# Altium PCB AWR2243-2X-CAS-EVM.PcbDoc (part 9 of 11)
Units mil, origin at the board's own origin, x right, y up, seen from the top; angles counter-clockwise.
Board outline 5118.11 x 3937.01 mil, 8 copper layers (Layer 1 - Top Layer, Layer 2 - GND, Layer 3 - Signal (Sensitive), Layer 4 - GND / Signal, Layer 5 - Signal, Layer 6 - PWR / Signal, Layer 7 - GND, Layer 8 - Bottom Layer), stack 54.8 mil thick; 629 components, 407 nets, 2243 pads, 3950 vias.
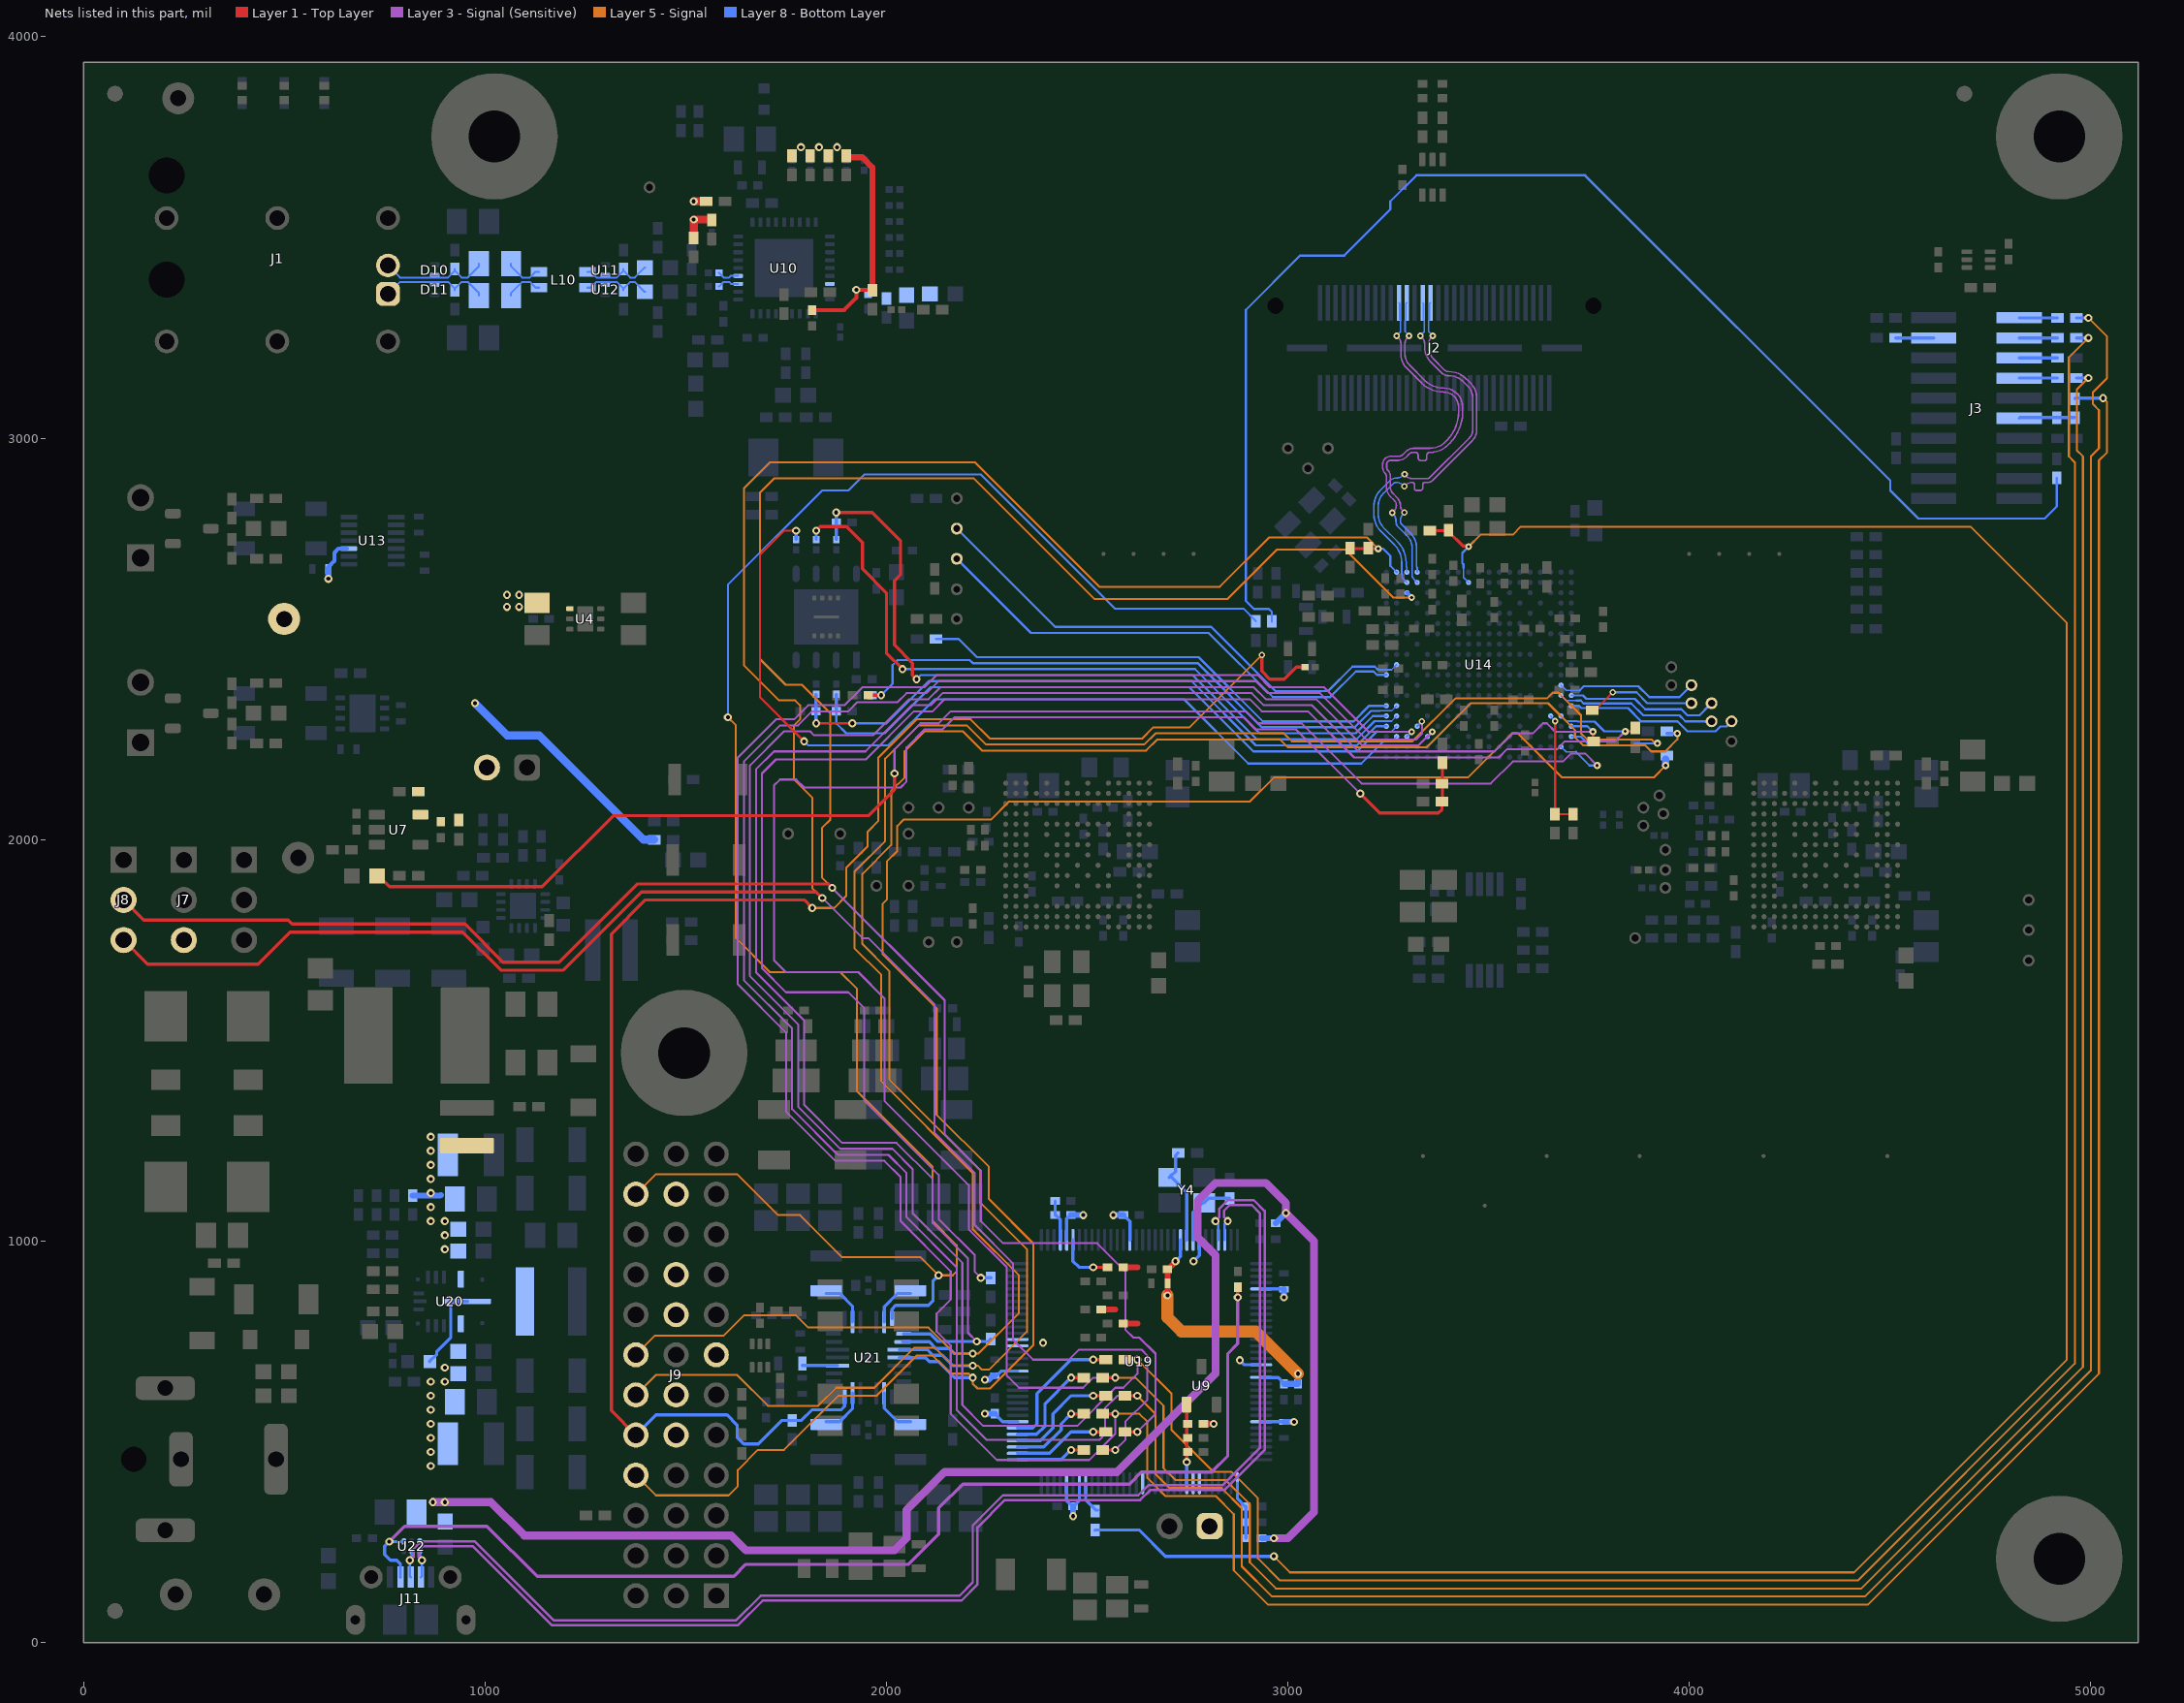
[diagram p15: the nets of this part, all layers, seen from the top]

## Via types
v1: diameter 13.78, hole 5.91, Layer 1 - Top Layer to Layer 2 - GND, tented top, 2104 vias
v2: diameter 20, hole 10, Layer 1 - Top Layer to Layer 8 - Bottom Layer, tented both sides, 831 vias
v3: diameter 7.87, hole 3.94, Layer 1 - Top Layer to Layer 2 - GND, tented top, 510 vias
v4: diameter 12, hole 6, Layer 1 - Top Layer to Layer 8 - Bottom Layer, tented both sides, 176 vias
v5: diameter 16, hole 8, Layer 1 - Top Layer to Layer 8 - Bottom Layer, tented both sides, 138 vias
v6: diameter 13.78, hole 5.91, Layer 1 - Top Layer to Layer 2 - GND, tented both sides, 88 vias
v7: diameter 18, hole 8, Layer 1 - Top Layer to Layer 8 - Bottom Layer, tented both sides, 41 vias
v8: diameter 22, hole 12, Layer 1 - Top Layer to Layer 8 - Bottom Layer, tented both sides, 36 vias
v9: diameter 19.68, hole 7.87, Layer 1 - Top Layer to Layer 8 - Bottom Layer, tented both sides, 26 vias

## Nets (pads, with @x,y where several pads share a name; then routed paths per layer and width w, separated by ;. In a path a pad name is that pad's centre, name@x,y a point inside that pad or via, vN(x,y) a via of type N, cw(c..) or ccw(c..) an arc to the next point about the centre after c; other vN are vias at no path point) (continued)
SOC_LVDS_TX2_N: J2.40 U14.V4 | length 951.9
  Layer 3 - Signal (Sensitive) w4: v5(3259.5,2814.5) 3264.34,2819.34 ccw(c3250.69,2833) 3270,2833 ccw(c3253.1,2833) 3265.06,2844.94 3255.61,2854.39 cw(c3281.21,2880) 3245,2880 3245,2905.76 ccw(c3234.76,2905.76) 3242,2913 cw(c3256.49,2927.49) 3236,2927.49 3236,2935 cw(c3256,2935) 3256,2955 3274.93,2955 ccw(c3274.93,2972.07) 3287,2960 3294.93,2967.93 cw(c3312,2950.86) 3312,2975 3354,2975 ccw(c3354,3028.11) 3391.56,2990.56 3396.03,2995.03 ccw(c3326.1,3064.97) 3425,3064.97 3425,3078 ccw(c3388,3078) 3388,3115 cw(c3388,3192.6) 3333.13,3137.73 3295.91,3174.95 cw(c3330.96,3210) 3281.39,3210 3281.39,3235 ccw(c3258.32,3235) v5@3274.64,3251.31 ; v5(3270.94,3255) v5@3274.63,3251.31
  Layer 8 - Bottom Layer w4: v5(3259.5,2814.5) 3261.93,2812.07 cw(c3244.86,2795) 3269,2795 3269,2792.78 ccw(c3289.12,2792.78) 3274.89,2778.55 3298.22,2755.22 cw(c3272.07,2729.07) 3309.05,2729.07 3309.05,2661 ccw(c3326.77,2661) 3314.25,2648.46 U14.V4@3321.85,2640.87 ; v5(3270.94,3255) 3270.94,3256 3280.67,3265.72 3280.67,3293.5 3278.56,3295.61 3278.56,3335.66 J2.40@3276.42,3337.8
SOC_LVDS_TX2_P: J2.38 U14.W4 | length 952
  Layer 3 - Signal (Sensitive) w4: v5(3290,2815) 3285.66,2819.34 cw(c3299.31,2833) 3280,2833 ccw(c3253.1,2833) 3272.12,2852.02 3262.68,2861.46 cw(c3281.21,2880) 3255,2880 3255,2905.76 ccw(c3234.76,2905.76) 3249.07,2920.07 cw(c3256.49,2927.49) 3246,2927.49 3246,2935 cw(c3256,2935) 3256,2945 3274.93,2945 ccw(c3274.93,2972.07) 3294.07,2952.93 3302,2960.86 cw(c3312,2950.86) 3312,2965 3316.84,2965 cw(c3316.84,2957.34) 3324.5,2957.34 3324.5,2951.24 ccw(c3331.24,2951.24) 3331.24,2944.5 3340.5,2944.5 ccw(c3340.5,2949.5) 3345.5,2949.5 3345.5,2957.34 cw(c3353.16,2957.34) 3353.16,2965 3354,2965 ccw(c3354,3028.11) 3398.63,2983.49 3403.1,2987.96 ccw(c3326.1,3064.97) 3435,3064.97 3435,3078 ccw(c3388,3078) 3388,3125 cw(c3388,3192.6) 3340.2,3144.8 3302.98,3182.02 cw(c3330.96,3210) 3291.39,3210 3291.39,3235 cw(c3315.08,3235) 3298.33,3251.76 v5(3301.57,3255)
  Layer 8 - Bottom Layer w4: 3282.67,2786.33 3306,2763 cw(c3272.07,2729.07) 3320.05,2729.07 3320.05,2680.23 3321.85,2678.43 U14.W4@3321.85,2666.46 ; 3282.66,2786.34 cw(c3289.12,2792.78) 3280,2792.78 3280,2795 cw(c3304.14,2795) 3287.07,2812.07 v5(3290,2815) ; J2.38@3296.1,3337.8 3293.96,3335.66 3293.96,3295.61 3291.67,3293.31 3291.67,3265.91 3301.57,3256 v5(3301.57,3255)
SOC_LVDS_TX3_N: J2.34 U14.V3 | length 952.6
  Layer 3 - Signal (Sensitive) w4: v5@3289.5,2910.5 3294.34,2905.66 ccw(c3308,2919.31) 3308,2900 3348,2900 ccw(c3348,2907.24) 3353.11,2902.11 3452.22,3001.22 ccw(c3433.44,3020) 3460,3020 3460,3102.15 ccw(c3421.72,3102.15) 3448.79,3129.21 3437.56,3140.44 ccw(c3400,3102.89) 3400,3156 cw(c3400,3180.49) 3382.69,3163.17 3356.24,3189.62 ; v5(3330,3255) v5@3333.69,3251.31 ; v5@3333.7,3251.31 cw(c3317.38,3235) 3340.44,3235 3340.44,3227.75 ccw(c3394.37,3227.75) 3356.24,3189.62
  Layer 8 - Bottom Layer w4: 3253.69,2894.24 3230.72,2871.28 ccw(c3271.09,2830.91) 3214,2830.91 3214,2810 ccw(c3271.94,2810) 3230.97,2769.03 3264.7,2735.3 cw(c3219.4,2690) 3283.46,2690 3283.46,2661 ccw(c3301.18,2661) 3288.66,2648.46 U14.V3@3296.26,2640.87 ; 3253.69,2894.25 cw(c3270,2877.93) 3270,2901 ccw(c3270,2925.14) 3287.07,2908.07 v5@3289.5,2910.5 ; v5(3330,3255) 3330,3256 3339.72,3265.72 3339.72,3293.5 3337.61,3295.61 3337.61,3335.66 J2.34@3335.47,3337.8
  other v5: 3290.5,2910.5
SOC_LVDS_TX3_P: J2.32 U14.W3 | length 952.5
  Layer 3 - Signal (Sensitive) w4: v5(3290,2880) 3294.34,2884.34 cw(c3308,2870.69) 3308,2890 3310,2890 cw(c3310,2885) 3315,2885 3315,2875 ccw(c3320,2875) 3320,2870 3329.55,2870 ccw(c3329.55,2876.45) 3336,2876.45 3336,2885 cw(c3341,2885) 3341,2890 3348,2890 ccw(c3348,2907.24) 3360.19,2895.05 3459.29,2994.15 ccw(c3433.44,3020) 3470,3020 3470,3102.15 ccw(c3421.72,3102.15) 3455.86,3136.28 3444.63,3147.52 ccw(c3400,3102.89) 3400,3166 cw(c3400,3180.49) 3389.77,3170.23 3363.29,3196.71 cw(c3394.37,3227.75) 3350.44,3227.75 3350.44,3235 cw(c3374.14,3235) 3357.39,3251.76 v5(3360.63,3255)
  Layer 8 - Bottom Layer w4: v5(3290,2880) 3287.07,2882.93 ccw(c3270,2865.86) 3270,2890 ccw(c3270,2877.93) 3261.46,2886.46 3238.5,2863.5 ccw(c3271.09,2830.91) 3225,2830.91 3225,2810 ccw(c3271.94,2810) 3238.75,2776.81 3272.48,2743.08 cw(c3219.4,2690) 3294.46,2690 3294.46,2680.23 3296.26,2678.43 U14.W3@3296.26,2666.46 ; J2.32@3355.16,3337.8 3353.02,3335.66 3353.02,3295.61 3350.72,3293.31 3350.72,3265.91 3360.63,3256 v5(3360.63,3255)
SOC_MSS_SPIA_IRQ: TP16.1 U14.G18 | length 396.5
  Layer 8 - Bottom Layer w4: U14.G18@3680.12,2359.37 3692.91,2346.57 3717.95,2346.57
  Layer 8 - Bottom Layer w5.5: 3717.95,2346.57 3729.43,2346.57 3736.24,2339.76 3855.24,2339.76 3885,2310 3975,2310 3990,2295 TP16.1@4050,2295
SOC_MSS_SPIA_MISO: R34.1 TP14.1 | length 271.7
  Layer 1 - Top Layer w5.5: R34.1@3757.83,2322.69 3764.69,2322.69 v5(3809,2367)
  Layer 8 - Bottom Layer w5.5: v5(3809,2367) 3868,2367 3895,2340 TP14.1@4000,2340
SOC_MSS_SPIA_MOSI: TP13.1 U14.H18 | length 356
  Layer 8 - Bottom Layer w4: U14.H18@3680.12,2384.96 3692.91,2372.17 3726.51,2372.17
  Layer 8 - Bottom Layer w5.5: 3726.51,2372.17 3726.7,2372.17 3736.79,2382.26 3872.74,2382.26 3900,2355 3975,2355 4000,2380 TP13.1@4000,2385
SOC_MSS_SPIA_nCS0: TP17.1 U14.F19 | length 436.1
  Layer 8 - Bottom Layer w5.5: U14.F19@3705.71,2333.78 3724.61,2333.78 3730.63,2327.76 3847.24,2327.76 3880,2295 3970,2295 3995,2270 4065,2270 4077,2282 4092,2282 TP17.1@4105,2295
SOC_MSS_SPIA_SCLK: TP15.1 U14.G19 | length 380.1
  Layer 8 - Bottom Layer w5.5: U14.G19@3705.71,2359.37 3734.63,2359.37 3743.24,2350.76 3864.24,2350.76 3890,2325 3980,2325 3995,2310 4025,2310 4050,2335 TP15.1@4050,2340
SOC_MSS_UARTA_RX: J8.2 R80.1 U14.U3 | length 6777.7
  Layer 1 - Top Layer w8: J8.2@100,1850 150,1800 510,1800 520,1790 950,1790 1045,1695 1185,1695 1380,1890 1855,1890 v2(1865,1880) ; R80.1@2593.62,525 v2(2625,525)
  Layer 3 - Signal (Sensitive) w5: v2(1865,1880) 2145,1600 2145,1266.21 2235,1176.21 2235,1050 2290,995 2525,995 2595,925 2595,780 2615,760 2630,760 2670,720 2670,570 v2(2625,525)
  Layer 5 - Signal w5: v2(1865,1880) 1840,1905 1840,2030 1860,2050 1860,2315 1789,2386 1749,2386 1685,2450 1685,2865 1720,2900 2217.57,2900 2517.57,2600 2749.14,2600 2850,2600 2973,2723 3142,2723 3261.59,2603.41 v5(3308.13,2603.41)
  Layer 8 - Bottom Layer w10: U14.U3@3296.26,2615.28 v5(3308.13,2603.41)
SOC_nERROR_OUT: J9.15 R32.2 R225.1 U21.16 | length 4211
  Layer 1 - Top Layer w8: J9.15@1375.98,517.01 1315,577.99 1315,1765 1400,1850 1795,1850 v2(1815,1830) ; v5(2935,2460) 2935,2420 2955,2400 2990.39,2400 3020.39,2430 R32.2@3042.01,2430
  Layer 5 - Signal w5: v2(1815,1830) 1870,1830 1900,1860 1900,1930 1953,1983 1953,2020 1980,2047 1980,2205 2075,2300 2210,2300 2258,2252 2637,2252 2665,2280 2755,2280 v5(2935,2460)
  Layer 8 - Bottom Layer w8: J9.15@1375.98,517.01 1425.98,567 1603,567 1628.17,541.83 1628.17,511.83 1645,495 1681.38,495 1740,553.62 R225.1@1765.21,553.62 1788.62,553.62 1815,580 1887,580 1895.94,588.95 U21.16@1895.94,612.56
SOC_nRESET_FROM_EMU: R125.2 R142.1 | length 3448.3
  Layer 8 - Bottom Layer w5.5: R142.1@2960,2543.62 2960,2567.49 2952.49,2575 2915,2575 2895,2595 2895,3320 3030,3455 3140,3455 3255,3570 3255,3590 3320,3655 3740,3655 4500,2895 4500,2870 4570,2800 4885,2800 4915,2830 R125.2@4915,2901.38
SOC_nRESET_FROM_PMIC: J9.33 R143.1 U21.32 | length 4762
  Layer 5 - Signal w5: J9.33@1375.98,1117.01 1425.98,1167 1628,1167 1730,1065 1785,1065 1890,960 2085,960 v2(2130,915) 2165,915 2175,925 2175,990 2115,1050 2115,1185 1927,1373 1927,1628 1885,1670 1710,1670 1625,1755 1625,2285 v2(1605,2305)
  Layer 8 - Bottom Layer w5: v2(1605,2305) 1605,2635 1840,2870 1905,2870 1945,2910 2235,2910 2570,2575 2890,2575 2920,2545 R143.1@2920,2543.62
  Layer 8 - Bottom Layer w8: U21.32@2014.05,807.44 2014.06,831.06 2023,840 2105,840 2115.82,850.82 2115.82,900.82 v2(2130,915)
SOC_QSPI_CS: R234.2 R235.2 U14.F2 | length 1495.3
  Layer 1 - Top Layer w8: R235.2@1954.69,2360 1982.1,2360 1984.4,2362.3 v2(1986.69,2360)
  Layer 8 - Bottom Layer w4: 3228.29,2320.98 3257.87,2320.98 U14.F2@3270.67,2333.78
  Layer 8 - Bottom Layer w5.5: v2(1986.69,2360) 2015,2388.31 2015,2435 2027.66,2447.66 2207.34,2447.66 2215,2440 2775,2440 2935,2280 3165.83,2280 3206.81,2320.98 3228.29,2320.98
  Layer 8 - Bottom Layer w8: R234.2@1964.68,2360 v2(1986.69,2360)
SOC_QSPI_D0: R134.2 U14.C2 | length 2266.8
  Layer 1 - Top Layer w5.5: v2(1775,2770) 1745,2770 1685,2710 1685,2355 v2(1795,2245)
  Layer 8 - Bottom Layer w4: 3236.7,2244.21 3257.87,2244.21 U14.C2@3270.67,2257.01
  Layer 8 - Bottom Layer w5.5: v2@1800,2245 1800,2240 1805,2235 2005,2235 2120,2350 2435.83,2350 2741.36,2350 2901.36,2190 3182.48,2190 3236.7,2244.21
  Layer 8 - Bottom Layer w8: R134.2@1775,2747.99 v2(1775,2770)
SOC_QSPI_D1: R148.1 R151.1 U14.D2 | length 1617.9
  Layer 8 - Bottom Layer w4: 3222.29,2269.8 3257.87,2269.8 U14.D2@3270.67,2282.6
  Layer 8 - Bottom Layer w5.5: R151.1@1875.16,2320.16 1875.16,2289.84 1900,2265 1995,2265 2110,2380 2436.18,2380 2753.79,2380 2913.79,2220 3172.31,2220 3222.11,2269.8 3222.29,2269.8
  Layer 8 - Bottom Layer w8: R148.1@1875,2362.01 1875.16,2361.85 R151.1@1875.16,2320.16
SOC_QSPI_D2: R149.1 R152.1 U14.D1 | length 1621.8
  Layer 1 - Top Layer w5.5: v2(1825,2290) v2(1915,2290)
  Layer 8 - Bottom Layer w5.5: v2(1915,2290) 2000,2290 2105,2395 2454.68,2395 2760,2395 2920,2235 3171.75,2235 3219.35,2282.6 U14.D1@3245.08,2282.6
  Layer 8 - Bottom Layer w8: v2(1825,2290) 1824.84,2290.16 1824.84,2319.84 R152.1@1824.68,2320 1824.84,2320.16 1824.84,2361.85 R149.1@1825,2362.01
SOC_QSPI_D3: R130.1 R132.2 U14.E2 | length 1920.8
  Layer 1 - Top Layer w8: v2(1875,2815) 1965,2815 2035,2745 2035,2660 2020,2645 2020,2485 2065,2440 2065,2410 v2(2075,2400)
  Layer 8 - Bottom Layer w4: 3228.29,2295.39 3257.87,2295.39 U14.E2@3270.67,2308.19
  Layer 8 - Bottom Layer w5.5: v2(2075,2400) 2085,2410 2462.82,2410 2762.57,2410 2922.57,2250 3170.4,2250 3215.79,2295.39 3228.29,2295.39
  Layer 8 - Bottom Layer w8: R132.2@1875,2747.99 1875.16,2748.15 1875,2748.31 R130.1@1875,2784.69 ; v2(1875,2815) R130.1@1875,2784.69 ; R130.1@1875.31,2785 R130.1@1875,2784.69
SOC_QSPI_SCLK: R133.2 U14.E1 | length 1803.4
  Layer 1 - Top Layer w8: v2(1825,2770) 1835,2780 1900,2780 1940,2740 1940,2675 2000,2615 2000,2465 v2(2040,2425)
  Layer 8 - Bottom Layer w5.5: v2(2040,2425) 2768.79,2425 2928.79,2265 3168.48,2265 3211.67,2308.19 U14.E1@3245.08,2308.19
  Layer 8 - Bottom Layer w8: R133.2@1825,2747.99 v2(1825,2770)
SOC_SOP0_SOC_TDO: R37.1 R46.2 R48.1 R75.1 R118.2 | length 9701.8
  Layer 1 - Top Layer w8: R75.1@2538.62,660 v2(2570,660) ; v2(3180,2115) 3228,2067 3375,2067 3383.62,2075.62 R48.1@3383.62,2095 3385,2096.38 R37.1@3385,2191.38
  Layer 3 - Signal (Sensitive) w5: v2(2570,660) 2515,660 2490,635 2330,635 2300,665 2300,935 2205,1030 2205,1140 1995,1350 1995,1605 1930,1670 1750,1670 1720,1700 1720,2135 1735,2150 1775,2150 1795,2130 2035,2130 2050,2145 2050,2230 2095,2275 2140,2275 2170,2305 2890,2305 2920,2275 3020,2275 v2(3180,2115)
  Layer 5 - Signal w5: v2(2570,660) 2620,660 2690,590 2690,435 2720,405 2845,405 2905,345 2905,200 2970,135 4428.28,135 4980,686.72 4980,2955 4965,2970 4965,3121.38 v2(4993.62,3150)
  Layer 8 - Bottom Layer w8: R118.2@4963.62,3150 v2(4993.62,3150)
SOC_SOP1: R49.1 R50.2 U14.E17 | length 293.4
  Layer 1 - Top Layer w5.5: R49.1@3665,2063.62 R49.1@3665.18,2063.62 ; v5(3665.18,2295.39) R49.1@3665.18,2063.62 ; R50.2@3710,2063.62 R49.1@3665.18,2063.62
  Layer 8 - Bottom Layer w4: U14.E17@3654.53,2308.19 v5(3665.18,2295.39)
SOC_SOP2: R146.2 U14.F1 | length 1222.4
  Layer 8 - Bottom Layer w5.5: R146.2@2123.62,2500 2180,2500 2225,2455 2777.72,2455 2937.72,2295 3163.95,2295 3202.73,2333.78 U14.F1@3245.08,2333.78
SOC_SOP3_SOC_MSS_UARTB_TX: R19.2 R21.1 R228.1 U14.V9 | length 6347.7
  Layer 1 - Top Layer w8: R21.1@3353.62,2770 3398.62,2770 R19.2@3400,2771.38 3400,2767.44 3435.53,2731.91 3448.09,2731.91 v7(3450,2730)
  Layer 5 - Signal w5: v2(2965,215) 3005,175 4410,175 4940,705 4940,2540 4700,2780 3580,2780 3560,2760 3480,2760 v7(3450,2730)
  Layer 8 - Bottom Layer w4: 3437.01,2676.94 3437.01,2653.66 U14.V9@3449.8,2640.87
  Layer 8 - Bottom Layer w5.5: 3437.01,2676.94 3437.01,2685.68 3434.34,2688.35 3434.34,2714.34 v7(3450,2730)
  Layer 8 - Bottom Layer w8: R228.1@2519.37,280 R228.1@2520,280.63 2629.37,280.63 2695,215 v2(2965,215)
SOC_SOP4_SOC_MSS_UARTA_TX: J8.3 R20.1 R22.2 R82.1 U14.W2 | length 6991.3
  Layer 1 - Top Layer w8: J8.3@100,1750 160,1690 435,1690 515,1770 945,1770 1040,1675 1195,1675 1390,1870 1825,1870 v2(1840,1855) ; R82.1@2538.62,480 v2(2570,480) ; R22.2@3155,2726.62 3156.62,2725 v7(3225,2725)
  Layer 3 - Signal (Sensitive) w5: v2(1840,1855) 1940,1755 1955,1755 2120,1590 2120,1270 2220,1170 2220,1040 2315,945 2315,755 2365,705 2455,705 2480,730 2635,730 2650,715 2650,605 2595,550 2595,505 v2(2570,480)
  Layer 5 - Signal w5: v2(1840,1855) 1815,1880 1815,2105 1770,2150 1770,2285 1785,2300 1785,2335 1773,2347 1733,2347 1645,2435 1645,2875 1710,2940 2220,2940 2530,2630 2820,2630 2830,2630 2953,2753 3197,2753 v7(3225,2725)
  Layer 8 - Bottom Layer w5.5: v7(3225,2725) 3237,2725 3255,2707 3255,2682.13 U14.W2@3270.67,2666.46
SOC_SPIB_CS0: R36.1 R219.2 U14.D19 U21.2 | length 4305.1
  Layer 1 - Top Layer w5.5: v7(3759.58,2268.96) 3759.58,2246.8 R36.1@3761.38,2245
  Layer 3 - Signal (Sensitive) w5: v2(2225,750) 2203,772 2203,957 2115,1045 2115,1155 2025,1245 1890,1245 1795,1340 1795,1550 1675,1670 1675,2175 1720,2220 1947.57,2220 2062.57,2335 2110,2335 2140,2365 2910,2365 2940,2335 3060,2335 3175,2220 3515,2220 3560,2265 3610,2265 3635,2290 3645,2290 3666.04,2268.96 v7(3759.58,2268.96)
  Layer 8 - Bottom Layer w5.5: U14.D19@3705.71,2282.6 3745.94,2282.6 v7(3759.58,2268.96)
  Layer 8 - Bottom Layer w8: U21.2@2042.6,769.06 2109.94,769.06 2129,750 v2(2225,750) 2253.62,750 R219.2@2260,756.38
SOC_SPIB_CS1: R35.1 R216.2 U14.E18 | length 4115.7
  Layer 1 - Top Layer w5.5: v7(3840,2270) 3861.38,2270 R35.1@3866.38,2275
  Layer 3 - Signal (Sensitive) w5: v2(2235,908.62) 2220,923.62 2220,965 2130,1055 2130,1165 1945,1350 1945,1580 1905,1620 1750,1620 1690,1680 1690,2165 1725,2200 1948.79,2200 2068.79,2320 2115,2320 2145,2350 2905,2350 2935,2320 3050,2320 3165,2205 3525,2205 3545,2225 3670,2225 3690,2245 3815,2245 v7(3840,2270)
  Layer 8 - Bottom Layer w4: U14.E18@3680.12,2308.19 3692.91,2295.39 3721.2,2295.39 3722.5,2294.1
  Layer 8 - Bottom Layer w5.5: 3722.5,2294.1 3763.9,2294.1 3788,2270 v7(3840,2270)
  Layer 8 - Bottom Layer w8: v2(2235,908.62) R216.2@2260,908.62
SOC_SPIB_MISO: J9.21 U14.C19 U21.3 | length 5196.3
  Layer 5 - Signal w5: J9.21@1375.98,717.01 1423.98,765 1595,765 1645,815 1775,815 1805,785 2105,785 2170,720 v2(2215,720) 2229,720 2330,821 2330,915 2215,1030 2215,1170 1987,1398 1987,1663 1920,1730 1920,1920 1997,1997 1997,2202 2080,2285 2200,2285 2248,2237 2642,2237 2670,2265 2990,2265 3010,2245 3310,2245 3417,2352 3645,2352 3659,2366 3674,2366 3730,2310 3730,2265 3745,2250 3905,2250 3915,2240 v7(3920,2240)
  Layer 8 - Bottom Layer w5.5: U14.C19@3705.71,2257.01 3729.48,2257.01 3751.49,2235 3860,2235 3865,2240 v7(3920,2240)
  Layer 8 - Bottom Layer w8: U21.3@2040.63,749.37 2106.63,749.37 2123,733 2157,733 2170,720 v2(2215,720)
SOC_SPIB_MOSI: J9.12 R154.1 U21.5 | length 5023.7
  Layer 5 - Signal w5: J9.12@1375.98,417.01 1425.99,367 1607,367 1630,390 1630,430 1680,480 1745,480 1880,615 1975,615 2075,715 2115,715 2160,670 2205,670 v2(2215,660) 2215,645 2227,633 2258,633 2366,741 2366,994 2255,1105 2255,1185 2125,1315 2125,1580 1990,1715 1990,1840 2001,1851 2001,1946 2027,1972 2027,2034.5 2042.5,2050 2260,2050 2305,2095 2905,2095 2965,2155 3448,2155 3558,2265 3573,2265 3683,2155 3911,2155 v7(3941,2185)
  Layer 8 - Bottom Layer w8: U21.5@2031.77,710 2097,710 2107,700 2130,700 2170,660 v2(2215,660) ; R154.1@3941,2200.38 3940,2201.38 R154.1@3943.62,2205
  Layer 8 - Bottom Layer w18: v7(3941,2185) R154.1@3941,2200.38
SOC_SPIB_SCLK: J9.18 R153.1 U21.4 | length 5151.9
  Layer 5 - Signal w5: J9.18@1375.98,617.01 1425.98,667 1628,667 1705,590 1830,590 1875,635 1970,635 2070,735 2120,735 2165,690 v2(2215,690) 2228,690 2238,680 2255,680 2350,775 2350,980 2235,1095 2235,1175 2007,1403 2007,1673 1940,1740 1940,1915 2012,1987 2012,2122 2045,2155 2045,2220 2095,2270 2190,2270 2238,2222 2647,2222 2675,2250 2980,2250 3000,2230 3345,2230 3455,2340 3648,2340 3715,2273 3715,2255 3735,2235 3890,2235 3905,2220 3940,2220 3970,2250 v7(3970,2265)
  Layer 8 - Bottom Layer w8: U21.4@2031.77,729.68 2102.32,729.68 2116,716 2139,716 2165,690 v2(2215,690) ; R153.1@3943.62,2265 v7(3970,2265)
SOC_TCK: R78.1 R120.2 U14.C3 | length 9921.3
  Layer 1 - Top Layer w8: R78.1@2538.62,570 v2(2570,570)
  Layer 3 - Signal (Sensitive) w5: v2(2570,570) 2570,520 2505,455 2275,455 2160,570 2160,740 2125,775 2125,820 2160,855 2160,925 2035,1050 2035,1160 1995,1200 1872.57,1200 1750,1322.57 1750,1520 1630,1640 1630,2205 1725,2300 1770,2300 1805,2335 1895,2335 1940,2380 2043.79,2380 2095,2380 2125,2410 2925,2410 2955,2380 3090,2380 3201.12,2268.88 v5(3308.13,2268.88)
  Layer 5 - Signal w5: v2(2570,570) 2630,570 2650,550 2650,410 2695,365 2820,365 2865,320 2865,180 2950,95 4444.85,95 5020,670.15 5020,2945 5040,2965 5040,3090 v2(5030,3100)
  Layer 8 - Bottom Layer w5.5: U14.C3@3296.26,2257.01 v5(3308.13,2268.88)
  Layer 8 - Bottom Layer w8: R120.2@4960,3098.62 4961.38,3100 v2(5030,3100)
SOC_TDI: R73.1 R113.2 U14.C5 | length 9883.7
  Layer 1 - Top Layer w8: R73.1@2593.62,705 v2(2625,705)
  Layer 3 - Signal (Sensitive) w5: v2(2625,705) 2625,670 2590,635 2570,635 2475,540 2241,540 2189,592 2189,946 2065,1070 2065,1180 2015,1230 1885,1230 1780,1335 1780,1540 1660,1660 1660,2185 1745,2270 1810,2270 1820,2260 1966.21,2260 2056.21,2350 2105,2350 2135,2380 2915,2380 2945,2350 3070,2350 3185,2235 3325.43,2235 v5(3359.31,2268.88)
  Layer 5 - Signal w5: v2(2625,705) 2710,620 2710,530 2815,425 2860,425 2925,360 2925,210 2980,155 4420,155 4960,695 4960,2940 4945,2955 4945,3201.38 v2(4993.62,3250)
  Layer 8 - Bottom Layer w5.5: U14.C5@3347.44,2257.01 v5(3359.31,2268.88)
  Layer 8 - Bottom Layer w8: R113.2@4963.62,3250 v2(4993.62,3250)
SOC_TMS: R77.1 R110.2 U14.D4 | length 10077.5
  Layer 1 - Top Layer w8: R77.1@2593.62,615 v2(2625,615)
  Layer 3 - Signal (Sensitive) w5: v2(2625,615) 2575,615 2545,585 2545,520 2530,505 2250,505 2175,580 2175,935 2050,1060 2050,1170 2005,1215 1878.79,1215 1765,1328.79 1765,1530 1645,1650 1645,2195 1735,2285 1780,2285 1815,2320 1905,2320 1927.5,2342.5 2027.5,2342.5 2050,2365 2100,2365 2130,2395 2920,2395 2950,2365 3080,2365 3195,2250 3320,2250 3333.72,2263.72 v5(3333.72,2294.47)
  Layer 5 - Signal w5: v2(2625,615) 2670,570 2670,420 2705,385 2835,385 2885,335 2885,190 2960,115 4436.57,115 5000,678.43 5000,2955 5020,2975 5020,3070 5005,3085 5005,3115 5040,3150 5040,3253.62 v2(4993.62,3300)
  Layer 8 - Bottom Layer w5.5: U14.D4@3321.85,2282.6 v5(3333.72,2294.47)
  Layer 8 - Bottom Layer w8: R110.2@4963.62,3300 v2(4993.62,3300)
SPARE_0: J9.14
SPARE_1: J9.17
SPARE_2: J9.23
SPARE_3: J9.26
SPARE_4: J9.32
SPARE_5: J9.19
SW: C217.1 L20.1 U20.16 | length 211.3
  Layer 8 - Bottom Layer w8: C217.1@862.56,700 862.56,700.98 880,718.43 880,726 915,761 915,847.11 917.89,850 U20.16@956.32,850
SW_B1: L21.1 U21.11 | length 117.3
  Layer 8 - Bottom Layer w8: U21.11@1994.37,621.42 1994.37,583.63 2027.88,550.12 L21.1@2060,550.12
SW_B2: L22.1 U21.15 | length 117.9
  Layer 8 - Bottom Layer w8: L22.1@1850,550.12 1883.12,550.12 1915.63,582.63 U21.15@1915.63,621.42
SW_B3: L19.1 U21.27 | length 117.9
  Layer 8 - Bottom Layer w8: L19.1@1850,869.88 1883.12,869.88 1915.63,837.37 U21.27@1915.63,798.58
SW_B4: L18.1 U21.31 | length 117.3
  Layer 8 - Bottom Layer w8: U21.31@1994.37,798.58 1994.37,836.37 2027.88,869.88 L18.1@2060,869.88
TCK: J3.11 R120.1 R121.2 | length 139.1
  Layer 8 - Bottom Layer w8: J3.11@4821.5,3050 4822.87,3051.38 R120.1@4960,3051.38
TDI: J3.3 R113.1 | length 94.9
  Layer 8 - Bottom Layer w8: J3.3@4821.5,3250 R113.1@4916.38,3250
TDIS: J3.4 R114.2 | length 94.9
  Layer 8 - Bottom Layer w8: R114.2@4513.62,3250 J3.4@4608.5,3250
TDO: J3.7 R118.1 | length 94.9
  Layer 8 - Bottom Layer w8: J3.7@4821.5,3150 R118.1@4916.38,3150
TMS: J3.1 R110.1 | length 94.9
  Layer 8 - Bottom Layer w8: J3.1@4821.5,3300 R110.1@4916.38,3300
TRD1_N: L10.1 R100.1 R103.2 U11.2 | length 177.5
  Layer 8 - Bottom Layer w5: L10.1@1255.04,3414.69 1263.9,3414.69 1278.08,3400.5 1328.06,3400.5 R100.1@1345,3417.44 ; R100.1@1345,3421.38 R100.1@1345,3417.44 ; R103.2@1398.5,3425 1397.52,3425 1373.02,3400.5 1361.94,3400.5 R100.1@1345,3417.44
TRD1_P: L10.2 R106.2 R108.2 U12.2 | length 177.5
  Layer 8 - Bottom Layer w5: L10.2@1255.04,3375.32 1263.9,3375.32 1278.08,3389.5 1328.06,3389.5 R106.2@1345,3372.56 ; R106.2@1345,3368.62 R106.2@1345,3372.56 ; R108.2@1398.5,3365 1397.52,3365 1373.02,3389.5 1361.94,3389.5 R106.2@1345,3372.56
TRD2_N: C102.2 L10.4 | length 93.9
  Layer 8 - Bottom Layer w5: C102.2@1065,3435 1065,3428.5 1093,3400.5 1111.92,3400.5 1126.1,3414.69 L10.4@1134.96,3414.69
TRD2_P: C103.2 L10.3 | length 93.9
  Layer 8 - Bottom Layer w5: C103.2@1065,3355 1065.02,3361.52 1093,3389.5 1111.92,3389.5 1126.1,3375.32 L10.3@1134.96,3375.32
TRD3_N: C102.1 D10.1 J1.2 R101.2 | length 275
  Layer 8 - Bottom Layer w5: J1.2@758.42,3430.44 788.37,3400.5 908.06,3400.5 R101.2@925,3417.44 ; R101.2@925,3421.38 R101.2@925,3417.44 ; C102.1@985,3435 985,3428.5 957,3400.5 941.94,3400.5 R101.2@925,3417.44
TRD3_P: C103.1 D11.1 J1.1 R107.2 | length 275
  Layer 8 - Bottom Layer w5: J1.1@758.42,3359.57 788.35,3389.5 908.04,3389.5 R107.2@924.98,3372.56 ; R107.2@925,3368.62 925,3372.56 941.94,3389.5 957,3389.5 984.98,3361.52 C103.1@985,3355
TRD_N: R105.1 U10.13 | length 54.2
  Layer 8 - Bottom Layer w5: R105.1@1582.99,3412 1594.49,3400.5 1608,3400.5 1611.81,3404.32 U10.13@1630.83,3404.32
TRD_P: R109.1 U10.12 | length 54.6
  Layer 8 - Bottom Layer w5: R109.1@1582.99,3378 1594.49,3389.5 1608,3389.5 1612.87,3384.63 U10.12@1630.83,3384.63
VBAT: C16.1 C121.1 C193.1 C203.1 C206.1 C209.1 C214.1 C220.1 C224.1 C227.1 J7.3 L4.2 R169.2 R208.1 TP9.1 U4.1 U13.10 U20.2 U20.14 | length 764.2
  Layer 8 - Bottom Layer w10: C121.1@610,2675 610,2679.5 625,2694.5 625,2715 635.28,2725.28 655.91,2725.28 U13.10@655.94,2725.32
  Layer 8 - Bottom Layer w15: v2(610,2650) C121.1@610,2675 ; R208.1@820,1113.62 888.62,1113.62 890,1115
  Layer 8 - Bottom Layer w20: v2(975,2340) 1055,2260 1135,2260 1395,2000 R169.2@1421.38,2000
  other v2: 865,440 865,475 865,510 865,545 865,580 865,615 865,650 900,650 900,685 900,980 900,1015 865,1050 900,1050 865,1085 865,1120 865,1155 865,1190 865,1225 865,1260 1055,2580 1085,2580 1055,2610 1085,2610
VBUS_1_DETECT: C238.2 R230.2 R231.1 U19.1 | length 146.8
  Layer 8 - Bottom Layer w8: U19.1@2874.09,396.85 U19.1@2874.09,396.85 2874.16,358.44 2893.35,339.25 C238.2@2895.31,339.25 R231.1@2895.31,260
VDDC: C76.2 C80.1 C221.2 C222.2 U19.87 U19.115 | length 715.2
  Layer 1 - Top Layer w8: C76.2@2699.69,930 C76.2@2700,930
  Layer 1 - Top Layer w15: C76.2@2699.69,930 C76.2@2700,929.69 ; v2(2700,865) C80.1@2700,895 2700,928.65 2720,948.65 v2(2720,950)
  Layer 5 - Signal w30: v2(2700,865) 2700,810 2735,775 2920,775 v2(3025,670)
  Layer 8 - Bottom Layer w8: v2(2720,950) 2732.36,962.36 U19.87@2732.36,1003.15 ; U19.115@2933.15,660.63 2976.02,660.63 2990,646.65 C222.2@2990,644.69
  Layer 8 - Bottom Layer w15: C222.2@2990,644.69 C221.2@3025,644.69 v2(3025,670)
VDDIO_ETH: C104.1 C106.2 C112.1 R3.2 R4.2 R5.2 R6.2 R7.2 R8.2 R9.2 R11.2 R17.1 R236.2 U10.34 | length 689.8
  Layer 1 - Top Layer w10: R17.1@1815,3319.37 1894.37,3319.37 1925,3350 v2(1925,3370) 1963.62,3370 R11.2@1965,3368.62
  Layer 1 - Top Layer w15: R6.2@1900,3703.62 1903.62,3700 1940,3700 1965,3675 R11.2@1965,3368.62
  Layer 1 - Top Layer w20: R9.2@1520,3498.62 v2(1520,3545) 1563.62,3545 R8.2@1565,3543.62 ; v2(1520,3590) R7.2@1551.38,3590
  other v2: 1787,3725 1832,3725 1877,3725
VOUT_LDO: C84.1 U21.20 | length 88.2
  Layer 8 - Bottom Layer w8: C84.1@1790,690.31 U21.20@1878.23,690.32
VPP_EN: R55.2 U14.B18 | length 3511.9
  Layer 1 - Top Layer w8: R55.2@737.48,1910 737.48,1907.52 762,1883 1143,1883 1320,2060 1955,2060 2020,2125 v2(2020,2165)
  Layer 3 - Signal (Sensitive) w5: v2(2020,2165) 2020,2225 2085,2290 2130,2290 2160,2320 2895,2320 2925,2290 3033.79,2290 3183.79,2140 3505,2140 3560,2195 3685,2195 3705,2215 3740,2215 v7(3770,2185)
  Layer 8 - Bottom Layer w4: U14.B18@3680.12,2231.42 3692.91,2218.62 3717.49,2218.62
  Layer 8 - Bottom Layer w5.5: 3717.49,2218.62 3751.11,2185 v7(3770,2185)
VPP_LDO_OUT: C47.1 C49.1 P1.2 R51.2 U7.5
VTREF: J3.5 R117.1 | length 94.9
  Layer 8 - Bottom Layer w8: J3.5@4821.5,3200 R117.1@4916.38,3200
XDS_3V3: C205.2 C210.1 C218.1 C225.2 C228.1 C237.2 P2.1 R62.2 R69.2 R71.2 R79.2 R211.2 U19.7 U19.8 U19.16 U19.26 U19.28 U19.39 U19.47 U19.51 U19.52 U19.69 U19.79 U19.90 U19.101 U19.113 U19.122 | length 933.7
  Layer 1 - Top Layer w15: R69.2@2534.69,830 2570,830 ; R71.2@2589.69,795 2625,795 ; R62.2@2589.69,935 2625,935 ; R79.2@2789.69,545 v2(2815,545)
  Layer 8 - Bottom Layer w8: C225.2@2270,570.31 2270,570 2289.54,550.46 2303.29,550.46 2303.35,550.39 U19.39@2326.85,550.39 ; C218.1@2270,665 2274.5,665 2285.88,676.38 U19.47@2326.85,676.38 ; U19.28@2448.9,396.85 2448.9,353.82 2462.72,340 C237.2@2464.68,340 2466.65,340 2480.39,353.74 U19.26@2480.39,396.85 ; U19.69@2448.9,1003.15 2448.9,1056.18 2457.72,1065 R211.2@2459.68,1065 ; C205.2@2590,1065 2606.38,1048.62 U19.79@2606.38,1003.15 ; v2(2765,950) 2779.61,964.61 U19.90@2779.6,1003.15 ; v2(2880,703.5) 2891.38,692.13 U19.113@2933.15,692.13 ; U19.122@2933.15,550.39 2933.21,550.33 2989.67,550.33 C228.1@2990,550 ; U19.101@2933.15,881.1 C210.1@2990,881.1
  Layer 8 - Bottom Layer w15: v2(2245,570.31) C225.2@2270,570.31 ; v2(2245,655) 2255,655 2265,665 C218.1@2270,665 ; R211.2@2459.68,1065 v2(2490,1065) ; v2(2464.69,315) C237.2@2464.68,340 ; v2(2565,1065) C205.2@2590,1065 ; C228.1@2990,550 v2(3015,550) ; v2(2990,860) C210.1@2990,880
  other v2: 2390,747
XDSET_1_D_N: J11.2 U19.93 U22.1 | length 3368.8
  Layer 3 - Signal (Sensitive) w6: v2(843,205) 834,214 834,229 845,240 970,240 1167,43 1629.97,43 1691.97,105 2186.97,105 2227,145.03 2227,287 2295,355 2631.97,355 2656.97,380 2841.97,380 2942,480.03 2942,1074.97 2914.97,1102 2850.03,1102 2829,1080.97 2829,1060 2819.45,1050.45 v2(2819.45,1050)
  Layer 8 - Bottom Layer w6: U22.1@839.68,229.17 837.69,227.17 837.69,210.31 v2(843,205) 843,165.56 J11.2@840.59,163.15 ; v2(2819.45,1050) 2826.85,1042.6 U19.93@2826.85,1003.15
XDSET_1_D_P: J11.3 U19.94 U22.2 | length 3327.5
  Layer 3 - Signal (Sensitive) w6: v2(813,205) 822,214 822,233.97 840.03,252 974.97,252 1171.97,55 1625,55 1687,117 2182,117 2215,150 2215,291.97 2290.03,367 2627,367 2652,392 2837,392 2930,485 2930,1070 2910,1090 2855,1090 2841,1076 2841,1060 2850,1051 v2(2850,1050)
  Layer 8 - Bottom Layer w6: J11.3@815,163.15 813,165.15 v2(813,205) 818,210 818,226.19 U22.2@820,228.19 ; U19.94@2842.6,1003.15 2842.6,1042.6 v2(2850,1050)
XDSET_1_ID: J11.4 R64.1 U22.4 | length 2904
  Layer 1 - Top Layer w8: v2(2875,860) R64.1@2875,885.32
  Layer 3 - Signal (Sensitive) w8: v2(761.81,251.81) 800,290 1005,290 1130,165 1620,165 1650,195 2055,195 2130,270 2130,335 2190,395 2605,395 2635,425 2810,425 2850,465 2850,720 2875,745 v2(2875,860)
  Layer 8 - Bottom Layer w8: J11.4@789.41,163.15 789.41,195.59 780,205 765,205 750,220 750,240 v2(761.81,251.81) U22.4@798.31,251.81
XDSET_1_VBUS: C236.1 R212.2 R229.2 R231.2 U22.6 | length 3922.9
  Layer 3 - Signal (Sensitive) w20: v2(870,350) v2(900,350) 1015,350 1098,267 1613,267 1650,230 2020,230 2050,260 2050,330 2145,425 2575,425 2820,670 2820,965 2775,1010 2775,1100 2820,1145 2945,1145 2995,1095 v2(2995,1070) 3065,1000 3065,325 3000,260 v2(2965,260)
  Layer 8 - Bottom Layer w15: R231.2@2934.68,260 v2(2965,260) ; R212.2@2969.68,1045 2994.69,1070 v2(2995,1070)
XDSET_NRST: R62.1 U19.70 | length 144.8
  Layer 1 - Top Layer w8: v2(2515,935) R62.1@2550.32,935
  Layer 8 - Bottom Layer w8: U19.70@2464.64,1003.15 2464.65,950.35 2480,935 v2(2515,935)
XDSET_OSC0: C194.1 U19.88 Y4.1 | length 248.8
  Layer 8 - Bottom Layer w8: Y4.1@2704.8,1158.5 Y4.1@2709.8,1163.5 ; Y4.1@2707.68,1163.5 Y4.1@2709.8,1163.5 ; C194.1@2726.38,1220 2720,1213.62 2720,1173.7 Y4.1@2709.8,1163.5 ; U19.88@2748.11,1003.15 2748.11,1121.89 2709.8,1160.2 Y4.1@2709.8,1163.5
XDSET_OSC1: C195.2 U19.89 Y4.3 | length 174.3
  Layer 8 - Bottom Layer w8: U19.89@2763.86,1003.15 2763.86,1071.89 2787.48,1095.51 Y4.3@2791.42,1095.51 2802.63,1106.73 C195.2@2855,1106.73
XDSET_TCK: R78.2 U19.35 | length 207.5
  Layer 1 - Top Layer w8: v2(2460,570) R78.2@2491.38,570
  Layer 8 - Bottom Layer w8: U19.35@2326.85,487.4 2392.4,487.4 2435,530 2435,545 v2(2460,570)
XDSET_TDI: R73.2 U19.38 | length 334
  Layer 1 - Top Layer w8: v2(2515,705) R73.2@2546.38,705
  Layer 8 - Bottom Layer w8: U19.38@2326.85,534.65 2364.65,534.65 2375,545 2375,620 2460,705 v2(2515,705)
XDSET_TDO: R75.2 U19.37 | length 255.2
  Layer 1 - Top Layer w8: v2(2460,660) R75.2@2491.38,660
  Layer 8 - Bottom Layer w8: U19.37@2326.85,518.9 2373.9,518.9 2395,540 2395,595 v2(2460,660)
XDSET_TMS: R77.2 U19.36 | length 286.4
  Layer 1 - Top Layer w8: v2(2515,615) R77.2@2546.38,615
  Layer 8 - Bottom Layer w8: U19.36@2326.85,503.15 2383.15,503.15 2415,535 2415,570 2460,615 v2(2515,615)
XDSET_UARTA_RX: R82.2 U19.33 | length 174.5
  Layer 1 - Top Layer w8: v2(2460,480) R82.2@2491.38,480
  Layer 8 - Bottom Layer w8: U19.33@2326.85,455.91 2435.91,455.91 v2(2460,480)
XDSET_UARTA_TX: R80.2 U19.34 | length 241.6
  Layer 1 - Top Layer w8: v2(2515,525) R80.2@2546.38,525
  Layer 8 - Bottom Layer w8: U19.34@2326.85,471.65 2406.65,471.65 2460,525 v2(2515,525)
XDSET_UARTB_TX: R228.2 U19.25 | length 81.7
  Layer 8 - Bottom Layer w8: U19.25@2496.14,396.85 2496.14,356.3 2522.44,330 R228.2@2526.38,330
XDSET_VBAT: C204.1 R211.1 U19.68 | length 103.3
  Layer 8 - Bottom Layer w8: C204.1@2420.31,1100 R211.1@2420.31,1065 2422.28,1065 2433.15,1054.13 U19.68@2433.15,1003.15
XDSET_VREFA: C90.2 C91.2 R79.1 U9.1 U19.9 | length 191.4
  Layer 1 - Top Layer w8: v2(2748.11,450) U9.1@2748.11,588.27
  Layer 8 - Bottom Layer w8: U19.9@2748.11,396.85 v2(2748.11,450)
XREF_CLK0: TP7.1 U14.J1 | length 1243
  Layer 8 - Bottom Layer w5.5: TP7.1@2175,2700 2360,2515 2802.57,2515 2962.57,2355 3105,2355 3169,2419 3213.27,2419 3221.72,2410.55 U14.J1@3245.08,2410.55
XREF_CLK1: TP6.1 U14.K2 | length 1297.2
  Layer 8 - Bottom Layer w4: 3224.28,2423.35 3257.87,2423.35 U14.K2@3270.67,2436.14
  Layer 8 - Bottom Layer w5.5: TP6.1@2175,2775 2420,2530 2808.79,2530 2968.79,2370 3100,2370 3161,2431 3216.44,2431 3224.09,2423.35 3224.28,2423.35
pads on no net: D10.1S D10.2S D11.1S D11.2S FID1.1 FID2.1 FID3.1 FID4.1 FID5.1 FID6.1 H1.1 H2.1 H3.1 H4.1 J1.ALIGN1 J1.ALIGN2 J2.1 J2.2 J2.3 J2.4 J2.5 J2.6 J2.7 J2.8 J2.9 J2.10 J2.11 J2.12 J2.14 J2.15 J2.16 J2.17 J2.19 J2.20 J2.21 J2.22 J2.23 J2.25 J2.27 J2.29 J2.31 J2.33 J2.35 J2.37 J2.39 J2.41 J2.43 J2.45 J2.47 J2.49 J2.51 J2.53 J2.55 J2.57 J2.59 J2.MH1 J2.MH2 J3.6 J3.17 J3.18 J3.19 J10.ALIGN J11.7 J11.8 LBL1.0 MP1. MP2. MP3. MP4. U4.7@1250,2532.28 U4.7@1250,2567.72 U5.C13 U5.C14 U5.G13 U5.M14 U5.M15 U5.N14 U5.N15 U5.P1 U5.P2 U5.P3 U5.P8 U5.P9 U5.P10 U5.R2 U5.R10 U5.R11 U5.R12 U6.A14 U6.C13 U6.C14 U6.G13 U6.M14 U6.M15 U6.N14 U6.N15 U6.P1 U6.P2 U6.P3 U6.P8 U6.P9 U6.P10 U6.R2 U6.R10 U6.R11 U6.R12 U10.9 U10.17 U10.18 U10.19 U10.20 U10.21 U11.1S U11.2S U12.1S U12.2S U13.11 U14.B3 U14.H2 U14.P2 U14.R1 U14.R2 U14.U11 U14.V10 U14.V11 U14.W10 U14.W11 U14.W17 U15.9 U17.5 U17.7 U18.12 U19.2 U19.3 U19.4 U19.5 U19.6 U19.11 U19.12 U19.13 U19.14 U19.15 U19.18 U19.19 U19.20 U19.21 U19.22 U19.23 U19.24 U19.27 U19.29 U19.30 U19.31 U19.32 U19.40 U19.41 U19.42 U19.43 U19.44 U19.45 U19.46 U19.49 U19.50 U19.53 U19.54 U19.56 U19.57 U19.65 U19.67 U19.71 U19.72 U19.73 U19.74 U19.75 U19.76 U19.77 U19.78 U19.81 U19.82 U19.83 U19.84 U19.85 U19.86 U19.91 U19.92 U19.97 U19.98 U19.99 U19.100 U19.102 U19.103 U19.104 U19.105 U19.106 U19.107 U19.108 U19.109 U19.110 U19.111 U19.112 U19.116 U19.117 U19.118 U19.119 U19.120 U19.121 U19.123 U19.124 U19.125 U19.126 U19.127 U19.128

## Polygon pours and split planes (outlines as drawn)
FE2_VRF2_FILTERED on Layer 8 - Bottom Layer "Layer 8 - Bottom Layer-FE2_VRF2_FILTERED" (solid, remove dead copper, pour order 714): 2280,1575 2455,1400 4775,1400 4925,1550 4925,2080 4885,2120 4755,2120 4735,2100 4735,2055 4770,2020 4770,1625 4660,1515 2595,1515 2425,1685 2165,1685 2150,1700 1875,1700 1745,1570 1745,1390 1785,1350 1860,1350 1900,1310 1910,1300 1985,1300 1995,1310 1995,1347 1975,1367 1975,1590 1995,1610 2185,1610 2220,1575
1V8 on Layer 8 - Bottom Layer "Layer 8 - Bottom Layer-1V8" (solid, remove dead copper, pour order 678): 1540,230 1560,250 2240,250 2265,275 2265,325 2250,340 2020,340 2015,345 2015,370 2005,380 1970,380 1965,385 1965,440 2000,475 2255,475 2365,365 2365,115 2320,70 1560,70 1540,90
1V0_B on Layer 8 - Bottom Layer "Layer 8 - Bottom Layer-1V0_B" (solid, remove dead copper, pour order 672): 1560,1065 1610,1065 1650,1105 1650,1155 1660,1165 2250,1165 2265,1150 2265,1090 2255,1080 2020,1080 2015,1075 2015,1060 1995,1040 1970,1040 1965,1035 1965,970 1995,940 2110,940 2265,940 2375,1050 2375,1210 2300,1285 1905,1285 1855,1335 1610,1335 1540,1265 1540,1085
GND on Layer 8 - Bottom Layer "LAYER_8_-_BOTTOM_LAYER_GND_P308" (solid, remove dead copper, pour order 308): 3493.84,2519.35 3517.84,2543.35 3517.84,2568.35 3527.3,2577.82 3545.3,2577.82 3551.84,2584.35 3597.92,2584.35 3609.84,2596.26 3629.81,2596.26 3637.46,2588.61 3637.46,2563.81 3595.15,2521.5 3573.07,2521.5 3563.18,2511.61 3563.18,2353.01 3572.84,2343.35 3589.83,2343.35 3597.83,2335.35 3597.83,2315.35 3588.83,2306.35 3563.18,2306.35 3553.84,2297.01 3553.84,2270.35 3545.84,2262.35 3520.09,2262.35 3513.67,2268.78 3513.67,2324.11 3509.84,2328.35 3437.84,2328.35 3437.84,2266.35 3420.83,2249.35 3398.3,2249.35 3391.84,2255.81 3391.84,2296.35 3387.81,2300.38 3341.86,2300.38 3337.84,2304.4 3337.83,2342.47 3342.8,2347.44 3379.84,2347.44 3386.84,2354.5 3386.84,2513.35 3367.29,2532.89 3367.29,2569.35 3358.84,2577.81 3358.84,2593.35 3372.84,2607.35 3385.83,2607.35 3439.83,2553.35 3439.84,2534.35 3454.84,2519.35
GND on Layer 8 - Bottom Layer "Layer 8 - Bottom Layer-GND" (solid, remove dead copper, pour order 734): 2636,1579 2685,1530 3660,1530 3735,1605 4200,1605 4245,1650 4245,1730 4225,1750 4145,1750 4135,1740 4105,1740 4100,1735 4100,1700 4080,1680 3735,1680 3710,1705 3700,1705 3690,1695 3690,1677.27 3602.73,1590 2845,1590 2785,1650 2785,1745 2780,1750 2710,1750 2705,1755 2705,1790 2667,1828 2640,1828 2636,1824
3V3 on Layer 6 - PWR / Signal "Layer 7 - PWR / Signal-3V3" (solid, remove dead copper, pour order 726): 30,30 5085,30 5085,3905 30,3905
VBAT on Layer 6 - PWR / Signal "Layer 7 - PWR / Signal-VBAT" (solid, remove dead copper, pour order 692): 855,1040 820,1075 170,1075 30,1215 30,2475 290,2735 770,2735 870,2635 1300,2635 1350,2585 1350,2375 1300,2325 890,2325 825,2390 605,2390 350,2135 350,1690 410,1630 870,1630 1005,1495 1005,430 990,415 870,415 855,430
FE1_1V8_FILTERED on Layer 6 - PWR / Signal "Layer 7 - PWR / Signal-FE1_1V8_FILTERED" (solid, remove dead copper, pour order 716): 2650,110 2595,55 2440,55 2415,30 1155,30 1090,95 1090,215 1115,240 1265,240 1335,170 2055,170 2090,135 2190,135 2250,195 2410,195 2465,250 2640,250 2650,240
FE1_VRF2_FILTERED on Layer 6 - PWR / Signal "Layer 7 - PWR / Signal-FE1_VRF2_FILTERED" (solid, remove dead copper, pour order 712): 1865,1285 1920,1230 2330,1230 2675,1575 2780,1575 2915,1710 2915,1985 2995,2065 2995,2315 3160,2480 3160,2640 3140,2660 3080,2660 3050,2630 3050,2530 3015,2495 2927,2495 2905,2473 2905,2115 2825,2035 2825,1745 2740,1660 2655,1660 2305,1310 2000,1310 1940,1370 1940,1585 1930,1595 1875,1595 1865,1585
1V2 on Layer 6 - PWR / Signal "Layer 7 - PWR / Signal-1V2" (solid, remove dead copper, pour order 710): 1700,450 1720,470 2235,470 2285,520 2285,855 2260,880 2260,1135 2685,1560 2795,1560 2930,1695 2930,1980 3010,2060 3010,2305 3120,2415 3235,2530 3370,2530 3385,2545 3385,2600 3395,2610 3450,2610 3465,2595 3485,2595 3490,2600 3490,2640 3497,2647 3497,2713 3480,2730 3480,2750 3480,2773 3500,2793 3500,2810 3506,2816 3514,2816 3520,2810 3520,2735 3520,2660 3520,2590 3575,2535 3620,2535 3625,2530 3650,2530 3655,2535 3695,2535 3730,2535 3740,2525 3740,2425 3725,2410 3640,2410 3623,2393 3623,2358 3600,2335 3540,2335 3493,2288 3442,2288 3425,2305 3400,2305 3360,2345 3270,2345 3110,2185 3110,2030 3064.29,1984.29 3064.29,1594.29 2890,1420 2750,1420 2465,1135 2465,1005 2490,980 2490,445 2395,350 1720,350 1700,370
FE2_1V8_FILTERED on Layer 6 - PWR / Signal "Layer 7 - PWR / Signal-FE2_1V8_FILTERED" (solid, remove dead copper, pour order 690): 2670,170 2690,190 2990,190 3100,300 3100,1120 3150,1170 4205,1170 4260,1225 4260,2075 4240,2095 4240,2845 4315,2920 4450,2920 4500,2870 4500,2795 4455,2750 4455,2455 4550,2360 4995,2360 5085,2270 5085,65 5085,30 4385,30 2690,30 2670,50
3V3_FLASH on Layer 6 - PWR / Signal "Layer 7 - PWR / Signal-3V3_FLASH" (solid, remove dead copper, pour order 688): 1935,2305 1915,2325 1810,2325 1790,2305 1740,2305 1715,2330 1715,2495 1770,2550 1770,2635 1735,2670 1735,2715 1765,2745 1965,2745 2005,2745 2015,2735 2015,2490 2050,2455 2050,2330 2025,2305
3V3_BUFFER on Layer 6 - PWR / Signal "Layer 6 - PWR / Signal-3V3_BUFFER" (solid, remove dead copper, pour order 722): 3360,1790 3375,1805 3590,1805 3605,1790 3605,1720 3625,1700 3670,1700 3680,1690 3680,1665 3670,1655 3370,1655 3360,1665
XDS_3V3 on Layer 1 - Top Layer "Layer 1 - Top Layer-XDS_3V3" (solid, remove dead copper, pour order 686): 2470,290 2525,345 2745,345 2765,325 2765,265 2780,250 2880,250 2895,265 2895,390 2930,425 3035,425 3070,460 3070,585 3035,620 2995,620 2960,655 2960,815 2995,850 3000,855 3000,900 2900.01,1000 2675,1000 2640,1035 2590,1085 2405,1085 2350,1030 2350,755 2275,680 2250,680 2235,665 2235,645 2245,635 2260,635 2270,625 2270,595 2260,585 2245,585 2235,575 2235,425 2290,370 2315,370 2360,370 2380,350 2380,315 2415,280 2460,280
GND on Layer 1 - Top Layer "Layer 1 - Top Layer-GND 5" (solid, remove dead copper, pour order 684): 2610,1100 2685,1175 2685,1566.02 2710,1591.02 2710,1660 2650,1660 2650,1723 2675,1748 2675,1772.23 2644,1803.23 2644,1814 2649,1819 2649,1824 2632,1841 2538,1841 2538,1830 2532,1824 2519,1824 2512,1817 2512,1777 2494,1759 2309,1759 2300,1750 2300,1730 2459,1730 2464,1725 2464,1667 2515,1667 2515,1550 2490,1525 2260,1525 2260,1100
1V2 on Layer 1 - Top Layer "Layer 1 - Top Layer-1V2 1" (solid, remove dead copper, pour order 682): 3581,2345 3586,2340 3619,2340 3624,2345 3624,2381 3656,2413 3674,2413 3685,2402 3721,2402 3724,2405 3724,2465 3707,2482 3707,2512 3712,2517 3771,2517 3795,2517 3799,2521 3799,2538 3795,2542 3775,2542 3767,2534 3668,2534 3656,2522 3656,2491 3649,2484 3632,2484 3625,2491 3625,2504 3620,2509 3586,2509 3581,2504
GND on Layer 1 - Top Layer "Layer 1 - Top Layer-GND 4" (solid, remove dead copper, pour order 680): 2560,2135 2560,2245 2670,2355 2795,2480 2802.99,2480 2927.99,2355 2995,2355 3125,2225 3125,1695 3155,1665 4390,1665 4410,1685 4410,1751 4373,1751 4346,1751 4341,1746 4341,1729 4337,1725 4313,1725 4313,1745 4327,1759 4360,1759 4375,1774 4375,1818 4381,1824 4400,1824 4405,1829 4405,1836 4410,1841 4422,1841 4448,1813 4480,1781 4480,1580 4460,1560 2995,1560 2975,1580 2975,1965 2920,2020 2920,2040 3010,2040 3035,2065 3035,2160 3005,2190 2800,2190 2782,2172 2695,2172 2658,2135 2626,2135 2621,2140 2612,2140 2607,2135 2601,2135 2596,2140 2587,2140 2582,2135
1V2 on Layer 1 - Top Layer "Layer 1 - Top Layer-1V2" (solid, remove dead copper, pour order 676): 1795,450 1870,375 1870,265 1835,230 1835,175 1815,155 1705,155 1685,175 1685,420 1715,450
1V0_A on Layer 1 - Top Layer "Layer 1 - Top Layer-1V0_A" (solid, remove dead copper, pour order 674): 1795,965 1875,1045 1875,1145 1890,1160 1945,1160 1955,1170 1955,1245 1945,1255 1680,1255 1670,1245 1670,975 1680,965
GND on Layer 1 - Top Layer "Layer 1 - Top Layer-GND 3" (solid, remove dead copper, pour order 670): 1815,590 1795,610 1795,670 1780,685 1745,685 1720,710 1720,720 1745,745 1765,745 1780,760 1780,795 1815,830 1925,830 1945,850 1945,930 1950,935 1960,935 1965,930 1965,850 1985,830 2095,830 2105,820 2105,740 2065,700 2065,665 2085,645 2105,625 2105,600 2095,590 1990,590 1965,565 1965,490 1960,485 1950,485 1945,490 1945,565 1920,590
NetC75_2 on Layer 1 - Top Layer "Layer 1 - Top Layer-NetC83_2" (solid, remove dead copper, pour order 668): 60,245 30,275 30,1305 50,1325 315,1325 335,1305 335,985 330,980 305,980 240,915 240,865 265,840 320,840 365,795 445,795 470,770 470,595 425,550 425,275 395,245
1V2 on Layer 1 - Top Layer " " (solid, pour order 216): 3522.84,2271.35 3522.84,2295.39 3494.86,2295.39 3494.82,2330.43 3454.93,2330.43 3454.93,2295.39 3425.84,2295.39 3425.84,2271.35
GND on Layer 1 - Top Layer "Layer 1 - Top Layer-GND 2" (solid, pour order 614): 3464.57,1221.85 3464.57,1098.43 3516.73,1098.43 3516.73,1221.85 4805.98,1221.85 4805.98,2000 4703.98,2102.01 4445.98,2102.01 4445.98,1922.01 4575.98,1922.01 4575.98,1587.01 2990.98,1587.01 2990.98,1989.02 2877.99,2102.01 2580.98,2102.01 2580.98,1922.01 2705.98,1922.01 2705.98,1617.01 2670,1581.02 2670,1187.01 2670,1160 3062,1160 3062,1221.85
GND on Layer 1 - Top Layer "Layer 1 - Top Layer-GND" (solid, remove dead copper, pour order 666): 2565.98,2077.01 2565.98,2227.01 2810.98,2472.01 2810.98,2702.17 2441.14,2702.17 2335.98,2597.01 2335.98,2077.01 2530.35,2077.01
GND on Layer 1 - Top Layer "Layer 1 - Top Layer-GND 1" (solid, remove dead copper, pour order 618): 4198.19,2077.01 4198.19,2236.81 3953.19,2481.81 3953.19,2702.17 4323.03,2702.17 4428.19,2597.01 4428.19,2077.01 4233.82,2077.01
GND on Layer 1 - Top Layer "Layer 1 - Top Layer-GND 6" (solid, remove dead copper, pour order 730): 2370,2080 2370,1865 2525,1865 2538,1852 2538,1835 2638,1835 2610,1863 2610,2072.99 2580.98,2102.01 2547.01,2102.01 2525,2080
GND on Layer 1 - Top Layer "Layer 1 - Top Layer-GND 7" (solid, remove dead copper, pour order 732): 4233.39,2080 4233.39,1865 4388.39,1865 4405,1848.39 4405,1830 4506.39,1830 4473.39,1863 4473.39,2082.61 4453.99,2102.01 4410.39,2102.01 4388.39,2080
GND on Layer 3 - Signal (Sensitive) "Layer 3 - Signal (Sensitive)-GND" (solid, remove dead copper, pour order 736): 20,20 5095,20 5095,3915 20,3915
5V on Layer 3 - Signal (Sensitive) "Layer 3 - Signal (Sensitive)-5V" (solid, remove dead copper, pour order 696): 900,2775 1025,2650 1025,2295 955,2225 955,2065 1030,1990 1120,1990 1185,1925 1185,1810 1310,1685 1310,1325 1345,1290 1615,1290 1650,1255 1650,380 1625,355 1060,355 925,490 925,1270 835,1360 535,1360 450,1445 450,2405 400,2455 400,2650 525,2775
3V3_LDO on Layer 3 - Signal (Sensitive) "Layer 3 - Signal (Sensitive)-3V3_LDO" (solid, remove dead copper, pour order 694): 1515,1730 1160,2085 1160,2210 1125,2245 1125,2680 945,2860 480,2860 300,3040 300,3550 560,3810 685,3810 1000,3495 1065,3495 1220,3650 1220,3790 1250,3820 1475,3820 1505,3790 1505,3715 1475,3685 1380,3685 1355,3660 1355,3520 1535,3340 1535,3160 1565,3130 1700,3130 1715,3115 1715,2825 1485,2595 1455,2565 1410,2565 1385,2540 1385,2475 1440,2420 1440,2225 1575,2090 1575,1940 1610,1905 1610,1745 1595,1730
GND on Layer 4 - GND / Signal "Layer 4 - GND / Signal-No Net" (solid, remove dead copper, pour order 728): 20,20 5095,20 5095,3915 20,3915
1V2_FILTERED on Layer 4 - GND / Signal "Layer 4 - GND / Signal-1V2_FILTERED" (solid, remove dead copper, pour order 708): 2175,145 1715,145 1630,230 1630,1170 1925,1465 1925,1660 1975,1710 1975,1820 2000,1845 2000,1940 2115,2055 2320,2055 2575,2055 2600,2030 2600,1815 2585,1800 2550,1800 2505,1845 2505,1870 2460,1915 2375,1915 2345,1885 2345,1785 2305,1745 2305,1575 2415,1465 3815,1465 3875,1405 4285,1405 4435,1555 4435,1780 4395,1820 4371,1844 4371,1849 4376,1854 4407,1854 4420,1867 4420,1900 4400,1920 4240,1920 4215,1895 4215,1790 4185,1760 4085,1760 4065,1780 4065,1935 4120,1990 4120,2060 4180,2120 4515,2120 4565,2070 4565,1425 4290,1150 2830,1150 2670,990 2500,990 2355,845 2355,560 2140,345 2140,280 2190,230 2190,160
FE1_1V8_FILTERED on Layer 4 - GND / Signal "Layer 4 - GND / Signal-FE1_1V8_FILTERED" (solid, remove dead copper, pour order 720): 1280,200 1315,235 1315,1235 1340,1260 1680,1260 1800,1380 1800,1585 1825,1610 1890,1610 1910,1630 1910,1670 1950,1710 1950,1910 2030,1990 2030,2030 2040,2040 2080,2040 2105,2065 2105,2090 2125,2110 2205,2110 2515,2110 2530,2095 2530,2020 2585,1965 2585,1815 2600,1800 2650,1800 2675,1825 2675,1855 2735,1915 2735,2155 2805,2225 3100,2225 3165,2290 3165,2560 3055,2670 2050.37,2670 1845,2459.36 1845,2400 1830,2385 1755,2385 975,1610 975,235 1010,200
1V8 on Layer 4 - GND / Signal "Layer 4 - GND / Signal-1V8" (solid, remove dead copper, pour order 706): 2255,145 2345,55 2660,55 2685,30 5085,30 5085,2660 4860,2885 3625,2885 3525,2785 3445,2785 3420,2760 3420,2690 3460,2650 3460,2605 3435,2580 3410,2580 3395,2595 3395,2630 3375,2650 3210,2650 3180,2620 3180,2580 3180,2335 3180,2190 3230,2140 3580,2140 3640,2200 4225,2200 4260,2165 4520,2165 4610,2075 4610,1425 4305,1120 3650,1120 3170,1120 3055,1005 3055,505 2890,340 2680,340 2630,290 2280,290 2255,265
GND on Layer 4 - GND / Signal "Layer 4 - GND / Signal-GND" (solid, remove dead copper, pour order 704): 2345,1765 2345,1880 2370,1905 2455,1905 2495,1865 2495,1840 2555,1780 2675,1780 2690,1795 2690,1845 2705,1860 2735,1860 2750,1875 2750,2125 2835,2210 3000,2210 3070,2140 3070,2095 3085,2080 3495,2080 3520,2105 3560,2105 3625,2170 4065,2170 4100,2135 4100,1995 4045,1940 4045,1765 4060,1750 4195,1750 4230,1785 4230,1895 4240,1905 4395,1905 4410,1890 4410,1870 4405,1865 4365,1865 4360,1860 4360,1845 4385,1820 4385,1815 4405,1795 4405,1560 4280,1435 3890,1435 3830,1495 3010,1495 2755,1495 2430,1495 2335,1590 2335,1755
GND on Layer 4 - GND / Signal "Layer 4 - GND / Signal-GND 1" (solid, remove dead copper, pour order 702): 3065,3290 3025,3250 3025,3070 3095,3000 3125,3000 3205,2920 3205,2820 3235,2790 3305,2790 3355,2840 3540,2840 3575,2875 3575,3210 3495,3290
GND on Layer 2 - GND "Layer 2 - GND-No Net" (solid, remove dead copper, pour order 612): 0,-2.99 5100.98,-2.99 5100.98,3937.01 -5.18,3937.01
GND on Layer 7 - GND "Layer 2 - GND-No Net" (solid, remove dead copper, pour order 724): 0,-2.99 5100.98,-2.99 5100.98,3937.01 -5.18,3937.01
GND on Layer 5 - Signal "Layer 5 - Signal-GND" (solid, remove dead copper, pour order 738): 20,20 5095,20 5095,3915 20,3915

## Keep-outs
Keep-Out Layer:
  text ".Layer_Name" at -2337.69,-846.49 h60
